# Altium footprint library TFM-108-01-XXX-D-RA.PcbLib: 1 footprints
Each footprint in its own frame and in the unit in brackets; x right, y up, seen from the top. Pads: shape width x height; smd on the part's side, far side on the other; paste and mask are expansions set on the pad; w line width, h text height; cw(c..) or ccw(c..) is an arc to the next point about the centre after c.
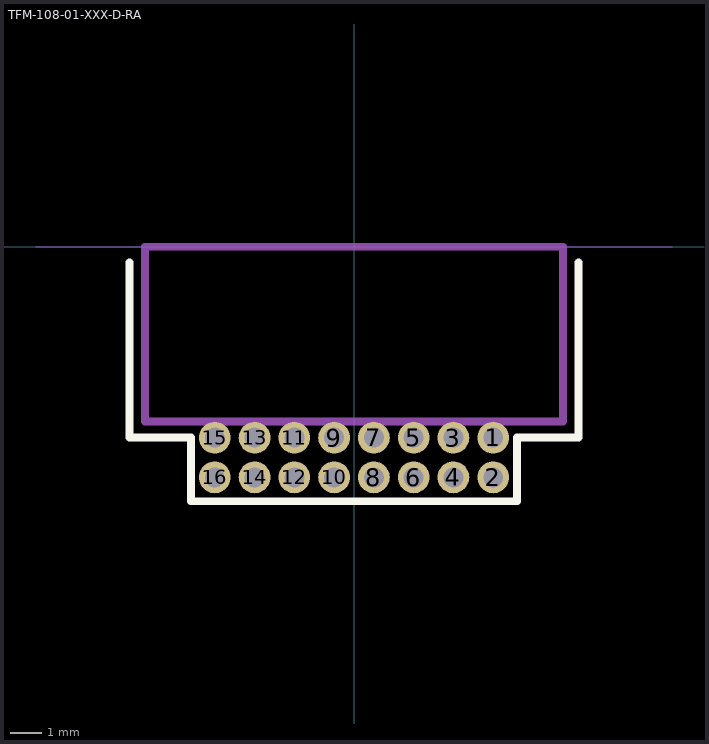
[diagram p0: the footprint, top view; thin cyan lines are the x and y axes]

## TFM-108-01-XXX-D-RA [mil]
pads (16):
  round 40 hole 25 mask+3: 1(175,-240) 2(175,-290) 3(125,-240) 4(125,-290) 5(75,-240) 6(75,-290) 7(25,-240) 8(25,-290) 9(-25,-240) 10(-25,-290) 11(-75,-240) 12(-75,-290) 13(-125,-240) 14(-125,-290) 15(-175,-240) 16(-175,-290)
Top Overlay:
  lines w10: -282.5,-20 -282.5,-240 -205,-240 -205,-320 205,-320 205,-240 282.5,-240 282.5,-20
Mechanical 1:
  lines w10: -262.5,-220 262.5,-220 262.5,0 -262.5,0 -262.5,-220
  text "J1" at -17.57,-117.19 h30
Mechanical 16:
  lines w1: -400,0 400,0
